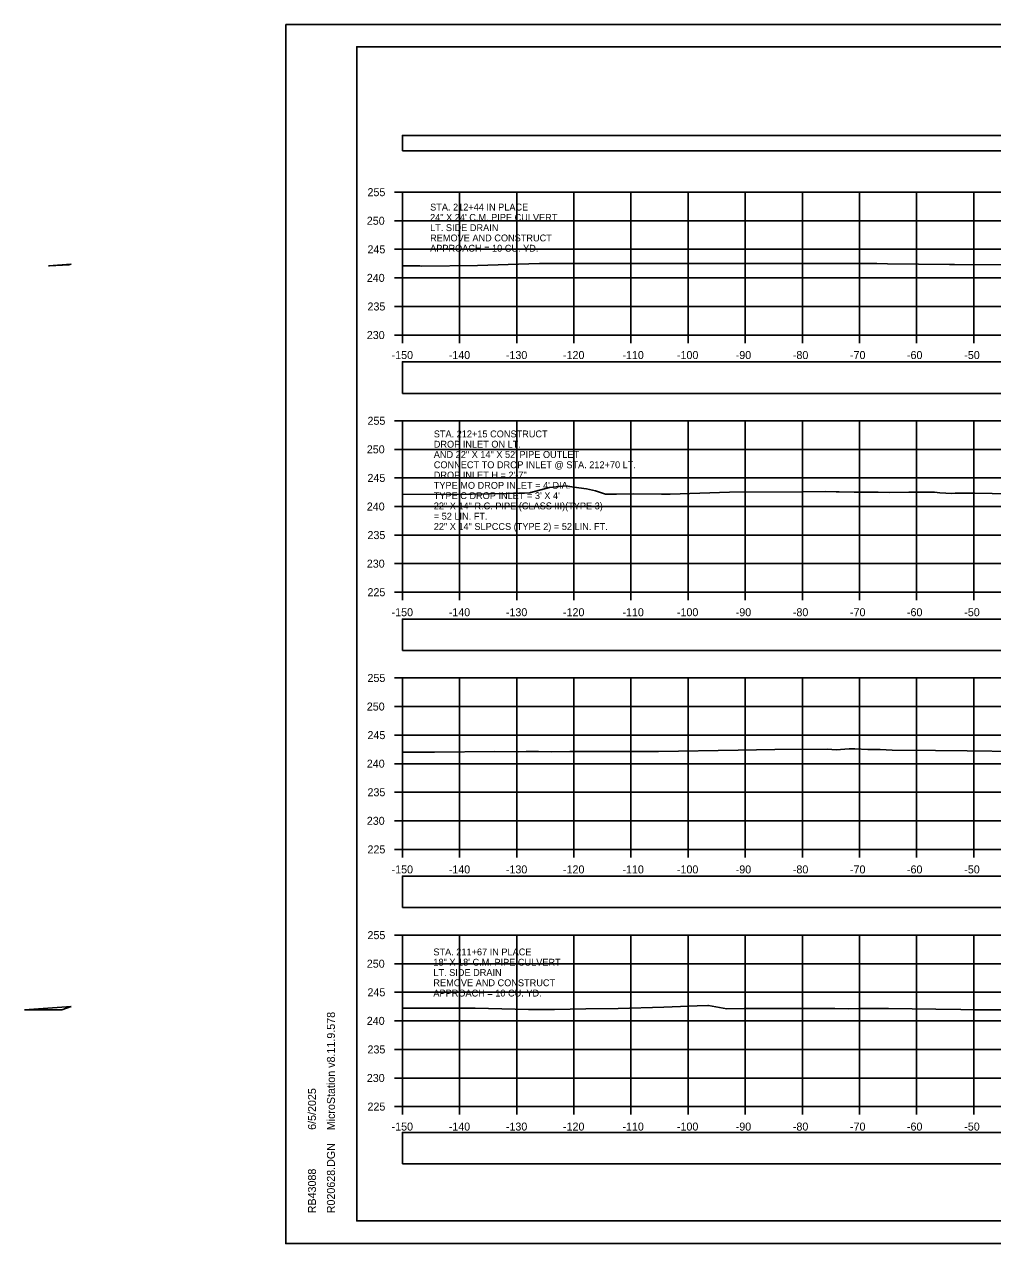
# Model space of a CAD drawing. Extents: x 1369627 to 1374022, y 380035 to 398173.
# Drawn here: x 1371882.4 to 1372051.8, y 382598.8 to 382812.2 of the extents above; entities that cross this region are included whole.
import ezdxf

# ---------------------------------------------------------------- set-up
doc = ezdxf.new("R2010")
doc.units = 0
for name, color, linetype in [('Default', 7, 'Continuous'), ('R_Axis', 7, 'Continuous'), ('R_Axis Annot', 7, 'Continuous'), ('R_Border', 7, 'Continuous'), ('R_Drive', 7, 'Continuous'), ('R_Exist Surface', 7, 'Continuous'), ('R_Grid', 7, 'Continuous'), ('R_No Plot', 7, 'Continuous'), ('R_Water', 7, 'Continuous'), ('R_Water Annot', 7, 'Continuous')]:
    doc.layers.add(name, color=color, linetype=linetype)

msp = doc.modelspace()

# ---------------------------------------------------------------- linework, layer by layer
at = {"layer": 'Default'}
for points in [[(1371948.53, 382790.04), (1372248.53, 382790.04), (1372248.53, 382792.75), (1371948.53, 382792.75)], [(1371948.53, 382747.61), (1372248.53, 382747.61), (1372248.53, 382753.14), (1371948.53, 382753.14)], [(1371948.53, 382702.6), (1372248.53, 382702.6), (1372248.53, 382708.12), (1371948.53, 382708.12)], [(1371948.53, 382657.63), (1372248.53, 382657.63), (1372248.53, 382663.15), (1371948.53, 382663.15)], [(1371948.53, 382612.78), (1372248.53, 382612.78), (1372248.53, 382618.3), (1371948.53, 382618.3)]]:
    msp.add_lwpolyline(points, close=True, dxfattribs=at)
at = {"layer": 'R_Axis'}
for p, q in [((1371947.13, 382782.81), (1371948.53, 382782.81)), ((1371948.53, 382757.81), (1371948.53, 382782.81)), ((1371947.13, 382777.81), (1371948.53, 382777.81)), ((1371947.13, 382772.81), (1371948.53, 382772.81)), ((1371947.13, 382767.81), (1371948.53, 382767.81)), ((1371947.13, 382762.81), (1371948.53, 382762.81)), ((1371947.13, 382757.81), (1371948.53, 382757.81)), ((1371948.53, 382757.81), (1372248.53, 382757.81)), ((1371948.53, 382756.41), (1371948.53, 382757.81)), ((1371958.53, 382756.41), (1371958.53, 382757.81)), ((1371968.53, 382756.41), (1371968.53, 382757.81)), ((1371978.53, 382756.41), (1371978.53, 382757.81)), ((1371988.53, 382756.41), (1371988.53, 382757.81)), ((1371998.53, 382756.41), (1371998.53, 382757.81)), ((1372008.53, 382756.41), (1372008.53, 382757.81)), ((1372018.53, 382756.41), (1372018.53, 382757.81)), ((1372028.53, 382756.41), (1372028.53, 382757.81)), ((1372038.53, 382756.41), (1372038.53, 382757.81)), ((1372048.53, 382756.41), (1372048.53, 382757.81)), ((1371947.13, 382742.81), (1371948.53, 382742.81)), ((1371948.53, 382712.81), (1371948.53, 382742.81)), ((1371947.13, 382737.81), (1371948.53, 382737.81)), ((1371947.13, 382732.81), (1371948.53, 382732.81)), ((1371947.13, 382727.81), (1371948.53, 382727.81)), ((1371947.13, 382722.81), (1371948.53, 382722.81)), ((1371947.13, 382717.81), (1371948.53, 382717.81)), ((1371947.13, 382712.81), (1371948.53, 382712.81)), ((1371948.53, 382712.81), (1372248.53, 382712.81)), ((1371948.53, 382711.41), (1371948.53, 382712.81)), ((1371958.53, 382711.41), (1371958.53, 382712.81)), ((1371968.53, 382711.41), (1371968.53, 382712.81)), ((1371978.53, 382711.41), (1371978.53, 382712.81)), ((1371988.53, 382711.41), (1371988.53, 382712.81)), ((1371998.53, 382711.41), (1371998.53, 382712.81)), ((1372008.53, 382711.41), (1372008.53, 382712.81)), ((1372018.53, 382711.41), (1372018.53, 382712.81)), ((1372028.53, 382711.41), (1372028.53, 382712.81)), ((1372038.53, 382711.41), (1372038.53, 382712.81)), ((1372048.53, 382711.41), (1372048.53, 382712.81)), ((1371947.13, 382697.81), (1371948.53, 382697.81)), ((1371948.53, 382667.81), (1371948.53, 382697.81)), ((1371947.13, 382692.81), (1371948.53, 382692.81)), ((1371947.13, 382687.81), (1371948.53, 382687.81)), ((1371947.13, 382682.81), (1371948.53, 382682.81)), ((1371947.13, 382677.81), (1371948.53, 382677.81)), ((1371947.13, 382672.81), (1371948.53, 382672.81)), ((1371947.13, 382667.81), (1371948.53, 382667.81)), ((1371948.53, 382667.81), (1372248.53, 382667.81)), ((1371948.53, 382666.41), (1371948.53, 382667.81)), ((1371958.53, 382666.41), (1371958.53, 382667.81)), ((1371968.53, 382666.41), (1371968.53, 382667.81)), ((1371978.53, 382666.41), (1371978.53, 382667.81)), ((1371988.53, 382666.41), (1371988.53, 382667.81)), ((1371998.53, 382666.41), (1371998.53, 382667.81)), ((1372008.53, 382666.41), (1372008.53, 382667.81)), ((1372018.53, 382666.41), (1372018.53, 382667.81)), ((1372028.53, 382666.41), (1372028.53, 382667.81)), ((1372038.53, 382666.41), (1372038.53, 382667.81)), ((1372048.53, 382666.41), (1372048.53, 382667.81)), ((1371947.13, 382652.81), (1371948.53, 382652.81)), ((1371948.53, 382622.81), (1371948.53, 382652.81)), ((1371947.13, 382647.81), (1371948.53, 382647.81)), ((1371947.13, 382642.81), (1371948.53, 382642.81)), ((1371947.13, 382637.81), (1371948.53, 382637.81)), ((1371947.13, 382632.81), (1371948.53, 382632.81)), ((1371947.13, 382627.81), (1371948.53, 382627.81)), ((1371947.13, 382622.81), (1371948.53, 382622.81)), ((1371948.53, 382622.81), (1372248.53, 382622.81)), ((1371948.53, 382621.41), (1371948.53, 382622.81)), ((1371958.53, 382621.41), (1371958.53, 382622.81)), ((1371968.53, 382621.41), (1371968.53, 382622.81)), ((1371978.53, 382621.41), (1371978.53, 382622.81)), ((1371988.53, 382621.41), (1371988.53, 382622.81)), ((1371998.53, 382621.41), (1371998.53, 382622.81)), ((1372008.53, 382621.41), (1372008.53, 382622.81)), ((1372018.53, 382621.41), (1372018.53, 382622.81)), ((1372028.53, 382621.41), (1372028.53, 382622.81)), ((1372038.53, 382621.41), (1372038.53, 382622.81)), ((1372048.53, 382621.41), (1372048.53, 382622.81))]:
    msp.add_line(p, q, dxfattribs=at)
at = {"layer": 'R_Border'}
for p, q in [((1371940.53, 382808.27), (1372256.71, 382808.27)), ((1371940.53, 382602.81), (1371940.53, 382808.27)), ((1371940.53, 382602.81), (1371940.53, 382602.81)), ((1372256.71, 382602.81), (1371940.53, 382602.81))]:
    msp.add_line(p, q, dxfattribs=at)
at = {"layer": 'R_Drive'}
for p, q in [((1371890.54, 382770.2), (1371886.56, 382769.94)), ((1371890.17, 382770.08), (1371890.54, 382770.2)), ((1371890.54, 382640.3), (1371882.36, 382639.76)), ((1371888.91, 382639.76), (1371890.54, 382640.3)), ((1371882.36, 382639.76), (1371888.91, 382639.76))]:
    msp.add_line(p, q, dxfattribs=at)
msp.add_lwpolyline([(1371886.56, 382769.94), (1371886.75, 382769.94), (1371890.17, 382770.08)], dxfattribs=at)
at = {"layer": 'R_Exist Surface'}
for points in [[(1371948.53, 382769.94), (1371951.59, 382769.94), (1371951.92, 382769.89), (1371961.65, 382769.97), (1371970.64, 382770.25), (1371972.53, 382770.34), (1371974.39, 382770.33), (1371993.65, 382770.32), (1371993.96, 382770.31), (1371999.91, 382770.32), (1372012.96, 382770.33), (1372014.76, 382770.31), (1372015.17, 382770.32), (1372031.58, 382770.32), (1372033.42, 382770.29), (1372044.3, 382770.15), (1372044.78, 382770.14), (1372045.18, 382770.14), (1372060.22, 382770.1)], [(1371948.53, 382729.91), (1371960.17, 382729.99), (1371960.71, 382729.99), (1371969.9, 382730.17), (1371970.85, 382730.19), (1371970.94, 382730.24), (1371971.02, 382730.26), (1371974.25, 382731.14), (1371977.11, 382731.42), (1371978.53, 382731.18), (1371980.75, 382730.91), (1371982.32, 382730.56), (1371984.05, 382729.98), (1371986.01, 382729.97), (1371988.91, 382730.04), (1371993.85, 382729.98), (1371994.75, 382729.97), (1371994.94, 382729.96), (1371995.39, 382729.97), (1372005.78, 382730.29), (1372018.62, 382730.4), (1372022.64, 382730.43), (1372024.43, 382730.39), (1372024.96, 382730.37), (1372027.58, 382730.32), (1372028.34, 382730.31), (1372030.91, 382730.31), (1372031.78, 382730.31), (1372033.71, 382730.28), (1372037.16, 382730.32), (1372041.67, 382730.29), (1372042.61, 382730.23), (1372044.68, 382730.11), (1372045.25, 382730.13), (1372048.74, 382730.15), (1372060.84, 382729.89)], [(1371948.53, 382684.84), (1371950.4, 382684.85), (1371954.13, 382684.83), (1371964.68, 382684.97), (1371968.81, 382684.91), (1371970.21, 382684.92), (1371972.33, 382684.95), (1371974.55, 382684.88), (1371977.85, 382684.97), (1371979.44, 382684.96), (1371982.67, 382684.95), (1371983.59, 382684.96), (1371990.02, 382684.96), (1371993.37, 382684.94), (1372007.28, 382685.16), (1372013.72, 382685.3), (1372022.96, 382685.34), (1372024.44, 382685.26), (1372026.7, 382685.4), (1372027.71, 382685.38), (1372030.01, 382685.29), (1372032.17, 382685.27), (1372034.27, 382685.19), (1372041.82, 382685.09), (1372047.35, 382685.06), (1372056.07, 382684.93)], [(1371948.53, 382640.03), (1371961.28, 382640.01), (1371970.62, 382639.82), (1371975.14, 382639.78), (1371980.66, 382639.89), (1371986.27, 382640), (1371994.3, 382640.22), (1372000.12, 382640.42), (1372001.99, 382640.47), (1372002.13, 382640.47), (1372005.34, 382639.89), (1372008.32, 382639.95), (1372012.18, 382640), (1372019.15, 382640), (1372021.11, 382639.99), (1372021.4, 382639.98), (1372023.12, 382639.98), (1372024.21, 382639.96), (1372026.62, 382639.94), (1372028.66, 382639.95), (1372030.47, 382639.98), (1372033.63, 382639.95), (1372041.91, 382639.83), (1372046.27, 382639.8), (1372048.59, 382639.76), (1372057.66, 382639.76)]]:
    msp.add_lwpolyline(points, dxfattribs=at)
at = {"layer": 'R_Grid'}
for p, q in [((1371948.53, 382782.81), (1372248.53, 382782.81)), ((1371948.53, 382757.81), (1371948.53, 382782.81)), ((1371958.53, 382757.81), (1371958.53, 382782.81)), ((1371968.53, 382757.81), (1371968.53, 382782.81)), ((1371978.53, 382757.81), (1371978.53, 382782.81)), ((1371988.53, 382757.81), (1371988.53, 382782.81)), ((1371998.53, 382757.81), (1371998.53, 382782.81)), ((1372008.53, 382757.81), (1372008.53, 382782.81)), ((1372018.53, 382757.81), (1372018.53, 382782.81)), ((1372028.53, 382757.81), (1372028.53, 382782.81)), ((1372038.53, 382757.81), (1372038.53, 382782.81)), ((1372048.53, 382757.81), (1372048.53, 382782.81)), ((1371948.53, 382777.81), (1372248.53, 382777.81)), ((1371948.53, 382772.81), (1372248.53, 382772.81)), ((1371948.53, 382767.81), (1372248.53, 382767.81)), ((1371948.53, 382762.81), (1372248.53, 382762.81)), ((1371948.53, 382757.81), (1372248.53, 382757.81)), ((1371948.53, 382742.81), (1372248.53, 382742.81)), ((1371948.53, 382712.81), (1371948.53, 382742.81)), ((1371958.53, 382712.81), (1371958.53, 382742.81)), ((1371968.53, 382712.81), (1371968.53, 382742.81)), ((1371978.53, 382712.81), (1371978.53, 382742.81)), ((1371988.53, 382712.81), (1371988.53, 382742.81)), ((1371998.53, 382712.81), (1371998.53, 382742.81)), ((1372008.53, 382712.81), (1372008.53, 382742.81)), ((1372018.53, 382712.81), (1372018.53, 382742.81)), ((1372028.53, 382712.81), (1372028.53, 382742.81)), ((1372038.53, 382712.81), (1372038.53, 382742.81)), ((1372048.53, 382712.81), (1372048.53, 382742.81)), ((1371948.53, 382737.81), (1372248.53, 382737.81)), ((1371948.53, 382732.81), (1372248.53, 382732.81)), ((1371948.53, 382727.81), (1372248.53, 382727.81)), ((1371948.53, 382722.81), (1372248.53, 382722.81)), ((1371948.53, 382717.81), (1372248.53, 382717.81)), ((1371948.53, 382712.81), (1372248.53, 382712.81)), ((1371948.53, 382697.81), (1372248.53, 382697.81)), ((1371948.53, 382667.81), (1371948.53, 382697.81)), ((1371958.53, 382667.81), (1371958.53, 382697.81)), ((1371968.53, 382667.81), (1371968.53, 382697.81)), ((1371978.53, 382667.81), (1371978.53, 382697.81)), ((1371988.53, 382667.81), (1371988.53, 382697.81)), ((1371998.53, 382667.81), (1371998.53, 382697.81)), ((1372008.53, 382667.81), (1372008.53, 382697.81)), ((1372018.53, 382667.81), (1372018.53, 382697.81)), ((1372028.53, 382667.81), (1372028.53, 382697.81)), ((1372038.53, 382667.81), (1372038.53, 382697.81)), ((1372048.53, 382667.81), (1372048.53, 382697.81)), ((1371948.53, 382692.81), (1372248.53, 382692.81)), ((1371948.53, 382687.81), (1372248.53, 382687.81)), ((1371948.53, 382682.81), (1372248.53, 382682.81)), ((1371948.53, 382677.81), (1372248.53, 382677.81)), ((1371948.53, 382672.81), (1372248.53, 382672.81)), ((1371948.53, 382667.81), (1372248.53, 382667.81)), ((1371948.53, 382652.81), (1372248.53, 382652.81)), ((1371948.53, 382622.81), (1371948.53, 382652.81)), ((1371958.53, 382622.81), (1371958.53, 382652.81)), ((1371968.53, 382622.81), (1371968.53, 382652.81)), ((1371978.53, 382622.81), (1371978.53, 382652.81)), ((1371988.53, 382622.81), (1371988.53, 382652.81)), ((1371998.53, 382622.81), (1371998.53, 382652.81)), ((1372008.53, 382622.81), (1372008.53, 382652.81)), ((1372018.53, 382622.81), (1372018.53, 382652.81)), ((1372028.53, 382622.81), (1372028.53, 382652.81)), ((1372038.53, 382622.81), (1372038.53, 382652.81)), ((1372048.53, 382622.81), (1372048.53, 382652.81)), ((1371948.53, 382647.81), (1372248.53, 382647.81)), ((1371948.53, 382642.81), (1372248.53, 382642.81)), ((1371948.53, 382637.81), (1372248.53, 382637.81)), ((1371948.53, 382632.81), (1372248.53, 382632.81)), ((1371948.53, 382627.81), (1372248.53, 382627.81)), ((1371948.53, 382622.81), (1372248.53, 382622.81))]:
    msp.add_line(p, q, dxfattribs=at)
at = {"layer": 'R_No Plot'}
for p, q in [((1371928.13, 382812.17), (1372261.46, 382812.17)), ((1371928.13, 382598.84), (1372261.46, 382598.84))]:
    msp.add_line(p, q, dxfattribs=at)
for points in [[(1371928.12, 382812.17), (1372261.46, 382812.17), (1372261.46, 382598.83), (1371928.12, 382598.83)], [(1372174.45, 382808.27), (1372194.07, 382808.27), (1372194.07, 382798.39), (1372210.18, 382798.39), (1372233.38, 382798.39), (1372233.38, 382765.72), (1372256.59, 382765.72), (1372256.71, 382602.81), (1371940.53, 382602.81), (1371940.53, 382808.27)]]:
    msp.add_lwpolyline(points, close=True, dxfattribs=at)

# ---------------------------------------------------------------- texts
at = {"layer": 'R_Axis Annot'}
for s, p in [('255', (1371942.42, 382782.11)), ('250', (1371942.3, 382777.11)), ('245', (1371942.42, 382772.11)), ('240', (1371942.3, 382767.11)), ('235', (1371942.42, 382762.11)), ('230', (1371942.3, 382757.11)), ('-150', (1371946.64, 382753.61)), ('-140', (1371956.64, 382753.61)), ('-130', (1371966.64, 382753.61)), ('-120', (1371976.64, 382753.61)), ('-110', (1371987.04, 382753.61)), ('-100', (1371996.58, 382753.61)), ('-90', (1372006.87, 382753.61)), ('-80', (1372016.87, 382753.61)), ('-70', (1372026.87, 382753.61)), ('-60', (1372036.84, 382753.61)), ('-50', (1372046.87, 382753.61)), ('255', (1371942.42, 382742.11)), ('250', (1371942.3, 382737.11)), ('245', (1371942.42, 382732.11)), ('240', (1371942.3, 382727.11)), ('235', (1371942.42, 382722.11)), ('230', (1371942.3, 382717.11)), ('225', (1371942.42, 382712.11)), ('-150', (1371946.64, 382708.61)), ('-140', (1371956.64, 382708.61)), ('-130', (1371966.64, 382708.61)), ('-120', (1371976.64, 382708.61)), ('-110', (1371987.04, 382708.61)), ('-100', (1371996.58, 382708.61)), ('-90', (1372006.87, 382708.61)), ('-80', (1372016.87, 382708.61)), ('-70', (1372026.87, 382708.61)), ('-60', (1372036.84, 382708.61)), ('-50', (1372046.87, 382708.61)), ('255', (1371942.42, 382697.11)), ('250', (1371942.3, 382692.11)), ('245', (1371942.42, 382687.11)), ('240', (1371942.3, 382682.11)), ('235', (1371942.42, 382677.11)), ('230', (1371942.3, 382672.11)), ('225', (1371942.42, 382667.11)), ('-150', (1371946.64, 382663.61)), ('-140', (1371956.64, 382663.61)), ('-130', (1371966.64, 382663.61)), ('-120', (1371976.64, 382663.61)), ('-110', (1371987.04, 382663.61)), ('-100', (1371996.58, 382663.61)), ('-90', (1372006.87, 382663.61)), ('-80', (1372016.87, 382663.61)), ('-70', (1372026.87, 382663.61)), ('-60', (1372036.84, 382663.61)), ('-50', (1372046.87, 382663.61)), ('255', (1371942.42, 382652.11)), ('250', (1371942.3, 382647.11)), ('245', (1371942.42, 382642.11)), ('240', (1371942.3, 382637.11)), ('235', (1371942.42, 382632.11)), ('230', (1371942.3, 382627.11)), ('225', (1371942.42, 382622.11)), ('-150', (1371946.64, 382618.61)), ('-140', (1371956.64, 382618.61)), ('-130', (1371966.64, 382618.61)), ('-120', (1371976.64, 382618.61)), ('-110', (1371987.04, 382618.61)), ('-100', (1371996.58, 382618.61)), ('-90', (1372006.87, 382618.61)), ('-80', (1372016.87, 382618.61)), ('-70', (1372026.87, 382618.61)), ('-60', (1372036.84, 382618.61)), ('-50', (1372046.87, 382618.61))]:
    msp.add_text(s, height=1.4, dxfattribs=at).set_placement(p)
at = {"layer": 'R_Border'}
for s, p in [('MicroStation v8.11.9.578', (1371936.72, 382618.67)), ('6/5/2025', (1371933.4, 382618.74)), ('R020628.DGN', (1371936.72, 382604.14)), ('RB43088', (1371933.4, 382604.14))]:
    msp.add_text(s, height=1.4, rotation=90, dxfattribs=at).set_placement(p)
at = {"layer": 'R_Water'}
for s, p in [('STA. 212+44 IN PLACE', (1371953.38, 382779.6)), ('24" X 24\' C.M. PIPE CULVERT', (1371953.38, 382777.8)), ('LT. SIDE DRAIN', (1371953.38, 382776)), ('REMOVE AND CONSTRUCT', (1371953.38, 382774.2)), ('APPROACH = 10 CU. YD.', (1371953.38, 382772.4)), ('STA. 211+67 IN PLACE', (1371953.95, 382649.27)), ('18" X 18\' C.M. PIPE CULVERT', (1371953.95, 382647.47)), ('LT. SIDE DRAIN', (1371953.95, 382645.67)), ('REMOVE AND CONSTRUCT', (1371953.95, 382643.87)), ('APPROACH = 10 CU. YD.', (1371953.95, 382642.07))]:
    msp.add_text(s, height=1.2, dxfattribs=at).set_placement(p)
at = {"layer": 'R_Water Annot'}
for s, p in [('STA. 212+15 CONSTRUCT', (1371954.02, 382739.91)), ('DROP INLET ON LT.', (1371954.02, 382738.11)), ('AND 22" X 14" X 52\' PIPE OUTLET', (1371954.02, 382736.31)), ('CONNECT TO DROP INLET @ STA. 212+70 LT.', (1371954.02, 382734.51)), ("TYPE MO DROP INLET = 4' DIA.", (1371954.02, 382730.91)), ('DROP INLET H = 2\'-7"', (1371954.02, 382732.71)), ("TYPE C DROP INLET = 3' X 4'", (1371954.02, 382729.11)), ('22" X 14" R.C. PIPE (CLASS III)(TYPE 3)', (1371954.02, 382727.31)), ('= 52 LIN. FT.', (1371954.02, 382725.51)), ('22" X 14" SLPCCS (TYPE 2) = 52 LIN. FT.', (1371954.02, 382723.71))]:
    msp.add_text(s, height=1.2, dxfattribs=at).set_placement(p)

doc.saveas('drawing.dxf')
